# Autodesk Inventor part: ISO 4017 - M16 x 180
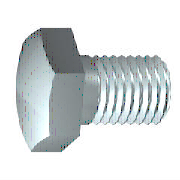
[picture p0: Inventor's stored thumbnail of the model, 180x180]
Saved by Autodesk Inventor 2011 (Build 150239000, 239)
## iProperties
IsCustomPart: 0
Created: 2010-02
Part Number: ISO 4017 - M16 x 180
Material: Stainless Steel, 440C
Description: Hexagon head screws
Document SubType Name: Modeling
Standard: ISO 4017
Designer: R. Koolhoven
Standard Revision: Third edition 1999-08-15
Standards Organization: ISO
Language: en-US
Size Designation: M16 x 180
Categories: <MemberInstance><Categories><Category DisplayName="Fasteners" InternalName="e4da775c-781d-43d5-af7c-5136215cf5a6" Mnemonic="FSTN"><Category DisplayName="Bolts"
Density: 7.75 g/cm^3
Mass: 318.011 g
Surface Area: 108.042 cm^2
Volume: 41.0336 cm^3
Author: R. Koolhoven
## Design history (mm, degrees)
body "Solid1"
workplane "Work Plane1"
revolve "Body" stored, may be unused: angle "d12" = 90 deg
sketch "Sketch2"
  geometry: L1 (0, 13.856)-(12, 6.928); L2 (12, 6.928)-(12, -6.928); L3 (12, -6.928)-(0, -13.856); L4 (0, -13.856)-(-12, -6.928); L5 (-12, -6.928)-(-12, 6.928); L6 (-12, 6.928)-(0, 13.856); 2 further points
  constraints: 12 end point, 1 coincident, 1 vertical, 11 other
  dimensions: "d11" = 24 distance between parallel lines of L5 L2 (= SW)
extrude "Head" join sketch "Sketch2" distance "d3" = 9.2 (= KOH - SD); taper "d4" = 0 deg
revolve "Chamfer1" stored, may be unused: angle "d21" = 90 deg
feature "Thread" dims "d15" = 174 (= GEL), "d16" = 0
chamfer "Chamfer2" distance "d6" = 1.2269 (= -0.5 x SPD + 0.5 x GD); stored, may be unused: second distance "d7" = 1.227 (computed from GUL), angle "d55" = 45 deg
sketch "Sketch1"
  geometry: L1 (0, 11)-(0, 8); L2 (6, 8)-(180, 8); L3 (180, 8)-(180, 0); L4 (180, 0)-(-0.8, 0); L5 (-36.96, 0)-(216.16, 0) reference; L6 (-0.8, 0)-(-0.8, 11); L7 (-0.8, 11)-(0, 11); L8 (6, 8)-(4.773, 8); L9 (4.773, 8)-(0, 8); L10 (0, -2.2)-(0, 13.2) reference
  constraints: 16 end point, 2 collinear, 2 perpendicular, 1 parallel
  dimensions: "d0" = 180 distance between parallel lines of L3 L1 (= NLG); "d1" = 174 distance from line of L2.start L3 (= GEL); "d2" = 16 diameter of L2 L4 (= GD); "d9" = 0.8001 distance between parallel lines of L6 L1 (computed from SD); "d10" = 22 diameter of L7 L4 (= SD2); "d13" = 1.227 distance of L2.start L8.end (computed from GAL); "d14" = 16 diameter of L9 L4 (= BDM)
sketch "Sketch4"
  geometry: L1 (-10, 12)-(-10, 13.856); L2 (-10, 13.856)-(-8.928, 13.856); L3 (-8.928, 13.856)-(-10, 12); L4 (-11.84, 0)-(1.04, 0) reference; L5 (-0.8, 13.856)-(-10, 13.856) reference; L6 (-10, 6.928)-(-10, 13.856) reference
  constraints: 6 end point, 2 collinear, 1 perpendicular, 1 vertical
  dimensions: "d5" = 30 deg angle of L3 L1 (= ANG1); "d19" = 24 diameter of L1.start L4 (= SW0)
other parameters: "NLG" = 180 [user parameter; used in 1 equation term], "GD" = 16 (= NND) [user parameter; used in 2 equation terms], "BDM" = 16 (= NND) [user parameter; used in 1 equation term], "KOH" = 10 [user parameter; used in 1 equation term], "GEL" = 174 [user parameter; used in 2 equation terms], "SW" = 24 [user parameter; used in 2 equation terms], "SW0" = 24 (= SW) [user parameter; used in 1 equation term], "SPD" = 13.5462 (= NND - 1.2269 x PTC) [user parameter; used in 1 equation term], "SD2" = 22 [user parameter; used in 2 equation terms], "SD" = 0.8 [user parameter; used in 2 equation terms], "ANG1" = 30 deg [user parameter; used in 1 equation term], "GAL" = 1.2269 (= 0.61345 x PTC) [user parameter; used in 1 equation term], "GUL" = 1.2269 (= 0.61345 x PTC) [user parameter; used in 1 equation term], "d8" = 0, "RR" = 0.6 [user parameter], "d57" = 0, "d58" = 0, "TPU" = 5 (computed from PTC) [user parameter], "GD1" = 13.5462 (= THREADDIA - 1.2269 x PTC) [user parameter], "THREADDIA" = 16 [user parameter; used in 1 equation term], "SDH" = 22 (= SD2) [user parameter], "SDHG" = 6 [user parameter], "TOA" = 30 deg [user parameter], "PTC" = 2 [user parameter; used in 5 equation terms], "NND" = 16 [user parameter; used in 3 equation terms], "E0" = 27.72 [user parameter]
